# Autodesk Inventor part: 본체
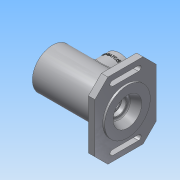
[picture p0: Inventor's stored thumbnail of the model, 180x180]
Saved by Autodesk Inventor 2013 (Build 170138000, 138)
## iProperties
Created: 2017-10
Part Number: 본체
Material: 알루미늄 6061
Document SubType Name: Modeling
Designer: Administrator
Density: 2.71 g/cm^3
Mass: 740.7 g
Surface Area: 652.733 cm^2
Volume: 273.321 cm^3
Author: Administrator
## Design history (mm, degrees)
sketch "스케치1"
  geometry: L1 (0, 0)-(0, 31); L2 (101, 16)-(101, 12.904); L3 (101, 12.904)-(100.3, 12.5); L4 (100.3, 12.5)-(93.7, 12.5); L5 (93.7, 12.5)-(93.7, 10); L6 (93.7, 10)-(91, 10); L7 (91, 10)-(91, 16.5); L8 (91, 16.5)-(86, 16.5); L9 (86, 16.5)-(86, 17.5); L10 (86, 17.5)-(75, 17.5); L11 (75, 17.5)-(75, 26); L12 (75, 26)-(37, 26); L13 (37, 26)-(37, 17.5); L14 (37, 17.5)-(26, 17.5); L15 (26, 17.5)-(26, 18.5); L16 (26, 18.5)-(24.25, 18.5); L17 (24.25, 18.5)-(24.25, 17.5); L18 (24.25, 17.5)-(21, 17.5); L19 (21, 17.5)-(21, 20); L20 (21, 20)-(12, 20); L21 (12, 20)-(12, 24); L22 (12, 24)-(9, 24); L23 (9, 24)-(9, 0); L24 (9, 0)-(0, 0); L25 (9, 0)-(96.109, 0); L26 (115, 22)-(115, 35); L27 (115, 22)-(101, 16); L28 (0, 31)-(102, 31); L29 (102, 31)-(102, 35); L30 (102, 35)-(115, 35)
  constraints: 60 end point, 12 parallel, 3 perpendicular, 1 collinear, 1 vertical
  dimensions: "d3" = 40 diameter of L20 L25; "d4" = 48 diameter of L22 L25; "d5" = 35 diameter of L18 L25; "d6" = 37 diameter of L16 L25; "d7" = 1.75 distance of L15.end L16.end; "d8" = 35 diameter of L14 L25; "d9" = 52 diameter of L12 L25; "d10" = 35 diameter of L10 L25; "d11" = 33 diameter of L8 L25; "d12" = 20 diameter of L6 L25; "d13" = 25 diameter of L4 L25; "d14" = 2.7 distance of L5.end L6.end; "d16" = 7.3 distance between parallel lines of L2 L5; "d17" = 0.7 horizontal distance of L2.end L3.end; "d19" = 32 diameter of L2.start L25; "d23" = 12 distance between parallel lines of L21 L1; "d24" = 3 distance of L21.end L22.end; "d25" = 21 distance between parallel lines of L19 L1; "d26" = 26 distance between parallel lines of L15 L1; "d27" = 60 distance between parallel lines of L9 L15; "d28" = 115 distance between parallel lines of L1 L26; "d30" = 30 deg angle of L4 L3; "d31" = 44 diameter of L26.start L25; "d32" = 14 distance between parallel lines of L2 L26; "d33" = 13 distance of L29.end L26.end; "d34" = 70 diameter of L30 L25; "d35" = 38 distance of L11.end L12.end; "d36" = 87.10866 distance of L23.end L25.end; "d37" = 11 distance of L13.end L14.end; "d38" = 62 diameter of L28 L25
revolve "회전1" sketch "스케치1" stored, may be unused: angle "d39" = 90 deg
sketch "스케치2"
  geometry: L1 (-58, -47)-(58, -47); L2 (58, -47)-(58, 47); L3 (58, 47)-(-58, 47); L4 (-58, 47)-(-58, -47); C1 r 31 at (0, 0) reference; 3 further points
  constraints: 8 end point, 2 midpoint, 2 parallel, 1 horizontal, 1 horizontal alignment, 1 perpendicular, 1 vertical alignment
  dimensions: "d40" = 116 distance of L1.start L1.end; "d42" = 94 distance of L3.end L1.start
extrude "돌출1" join sketch "스케치2" distance "d43" = 10; taper "d44" = 0 deg
sketch "스케치3"
  geometry: L1 (-50, 20)-(-50, -20); L2 (-42, -20)-(-42, 20); A1 r 4 centre (-46, -20) between (-50, -20) and (-42, -20); A2 r 4 centre (-46, 20) between (-42, 20) and (-50, 20); 2 further points
  constraints: 4 end point, 4 point on circle, 4 tangent, 2 centre point, 1 horizontal alignment, 1 midpoint, 1 parallel, 1 vertical, 1 vertical alignment
  dimensions: "d45" = 46 horizontal distance of point (0, 0) A2.centre; "d46" = 4 radius of A2; "d47" = 40 distance of A1.centre A2.centre
extrude "돌출2" cut sketch "스케치3" stored distance "d48" = 10; taper "d49" = 0 deg
hole "구멍1" diameter "d52" = 40.376; stored, may be unused: countersink angle "d56" = 90 deg, drill point angle "d58" = 0 deg; dims "d53" = 6, "d54" = 4, "d55" = 2, "d57" = 9, "d90" = 10, "d91" = 10
node "작업 평면1"
sketch "스케치4"
  geometry: L1 (0, 31)-(0, -31) reference; C1 r 25 at (-56, 0); 1 further point
  constraints: 1 centre point
  dimensions: "d60" = 50 diameter of C1; "d76" = 56 distance from line of C1.centre L1
extrude "돌출3" join sketch "스케치4" stored distance "d62" = 10; taper "d63" = 0 deg
hole "구멍2" diameter "d66" = 32; stored, may be unused: countersink angle "d70" = 90 deg, drill point angle "d72" = 0 deg; dims "d64" = 10, "d65" = 10, "d67" = 6, "d68" = 4, "d69" = 2, "d71" = 9
node "작업 평면2"
sketch "스케치5"
  geometry: L1 (31, 47)-(81, 47) reference; L2 (0, -31)-(0, 31) reference; 2 further points
  constraints: 1 other
  dimensions: "d74" = 10 distance from line of point (56, 37) L1; "d75" = 56 distance from line of point (56, 37) L2
feature "엠보싱1" sketch "스케치5" dims "d25" = 21, "d77" = 0.5, "d78" = 0
sketch "스케치6"
  geometry: 5 further points
  constraints: 3 vertical alignment, 1 other
  dimensions: "d80" = 41 distance of point (0, -20.5) point (0, 20.5); "d82" = 20.5 distance of point (0, 20.5) point (0, 0)
hole "구멍3" sketch "스케치6" at (0, 20.5), (0, -20.5) diameter "d83" = 2.459; stored, may be unused: countersink angle "d87" = 90 deg, drill point angle "d89" = 118 deg; dims "d84" = 6, "d85" = 4, "d86" = 2, "d88" = 8
chamfer "모따기1" distance "d92" = 20; stored, may be unused: second distance "d93" = 2, angle "d94" = 45 deg
fillet "모깎기1" dims "d95" = 0.3
chamfer "모따기2" distance "d96" = 1; stored, may be unused: second distance "d97" = 2, angle "d98" = 45 deg
fillet "모깎기2" dims "d99" = 3
fillet "모깎기3" dims "d100" = 3
node "솔리드1"
mirror "대칭1"
other parameters: "d59" = 47, "d73" = 106.75
